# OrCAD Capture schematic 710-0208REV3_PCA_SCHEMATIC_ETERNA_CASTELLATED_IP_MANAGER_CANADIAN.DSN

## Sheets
1 03) CASTLE: size Custom; title: PCA SCH, ETERNA IP CASTELLATED MNGR,CANADIAN; rev: 03; note: 710-0208
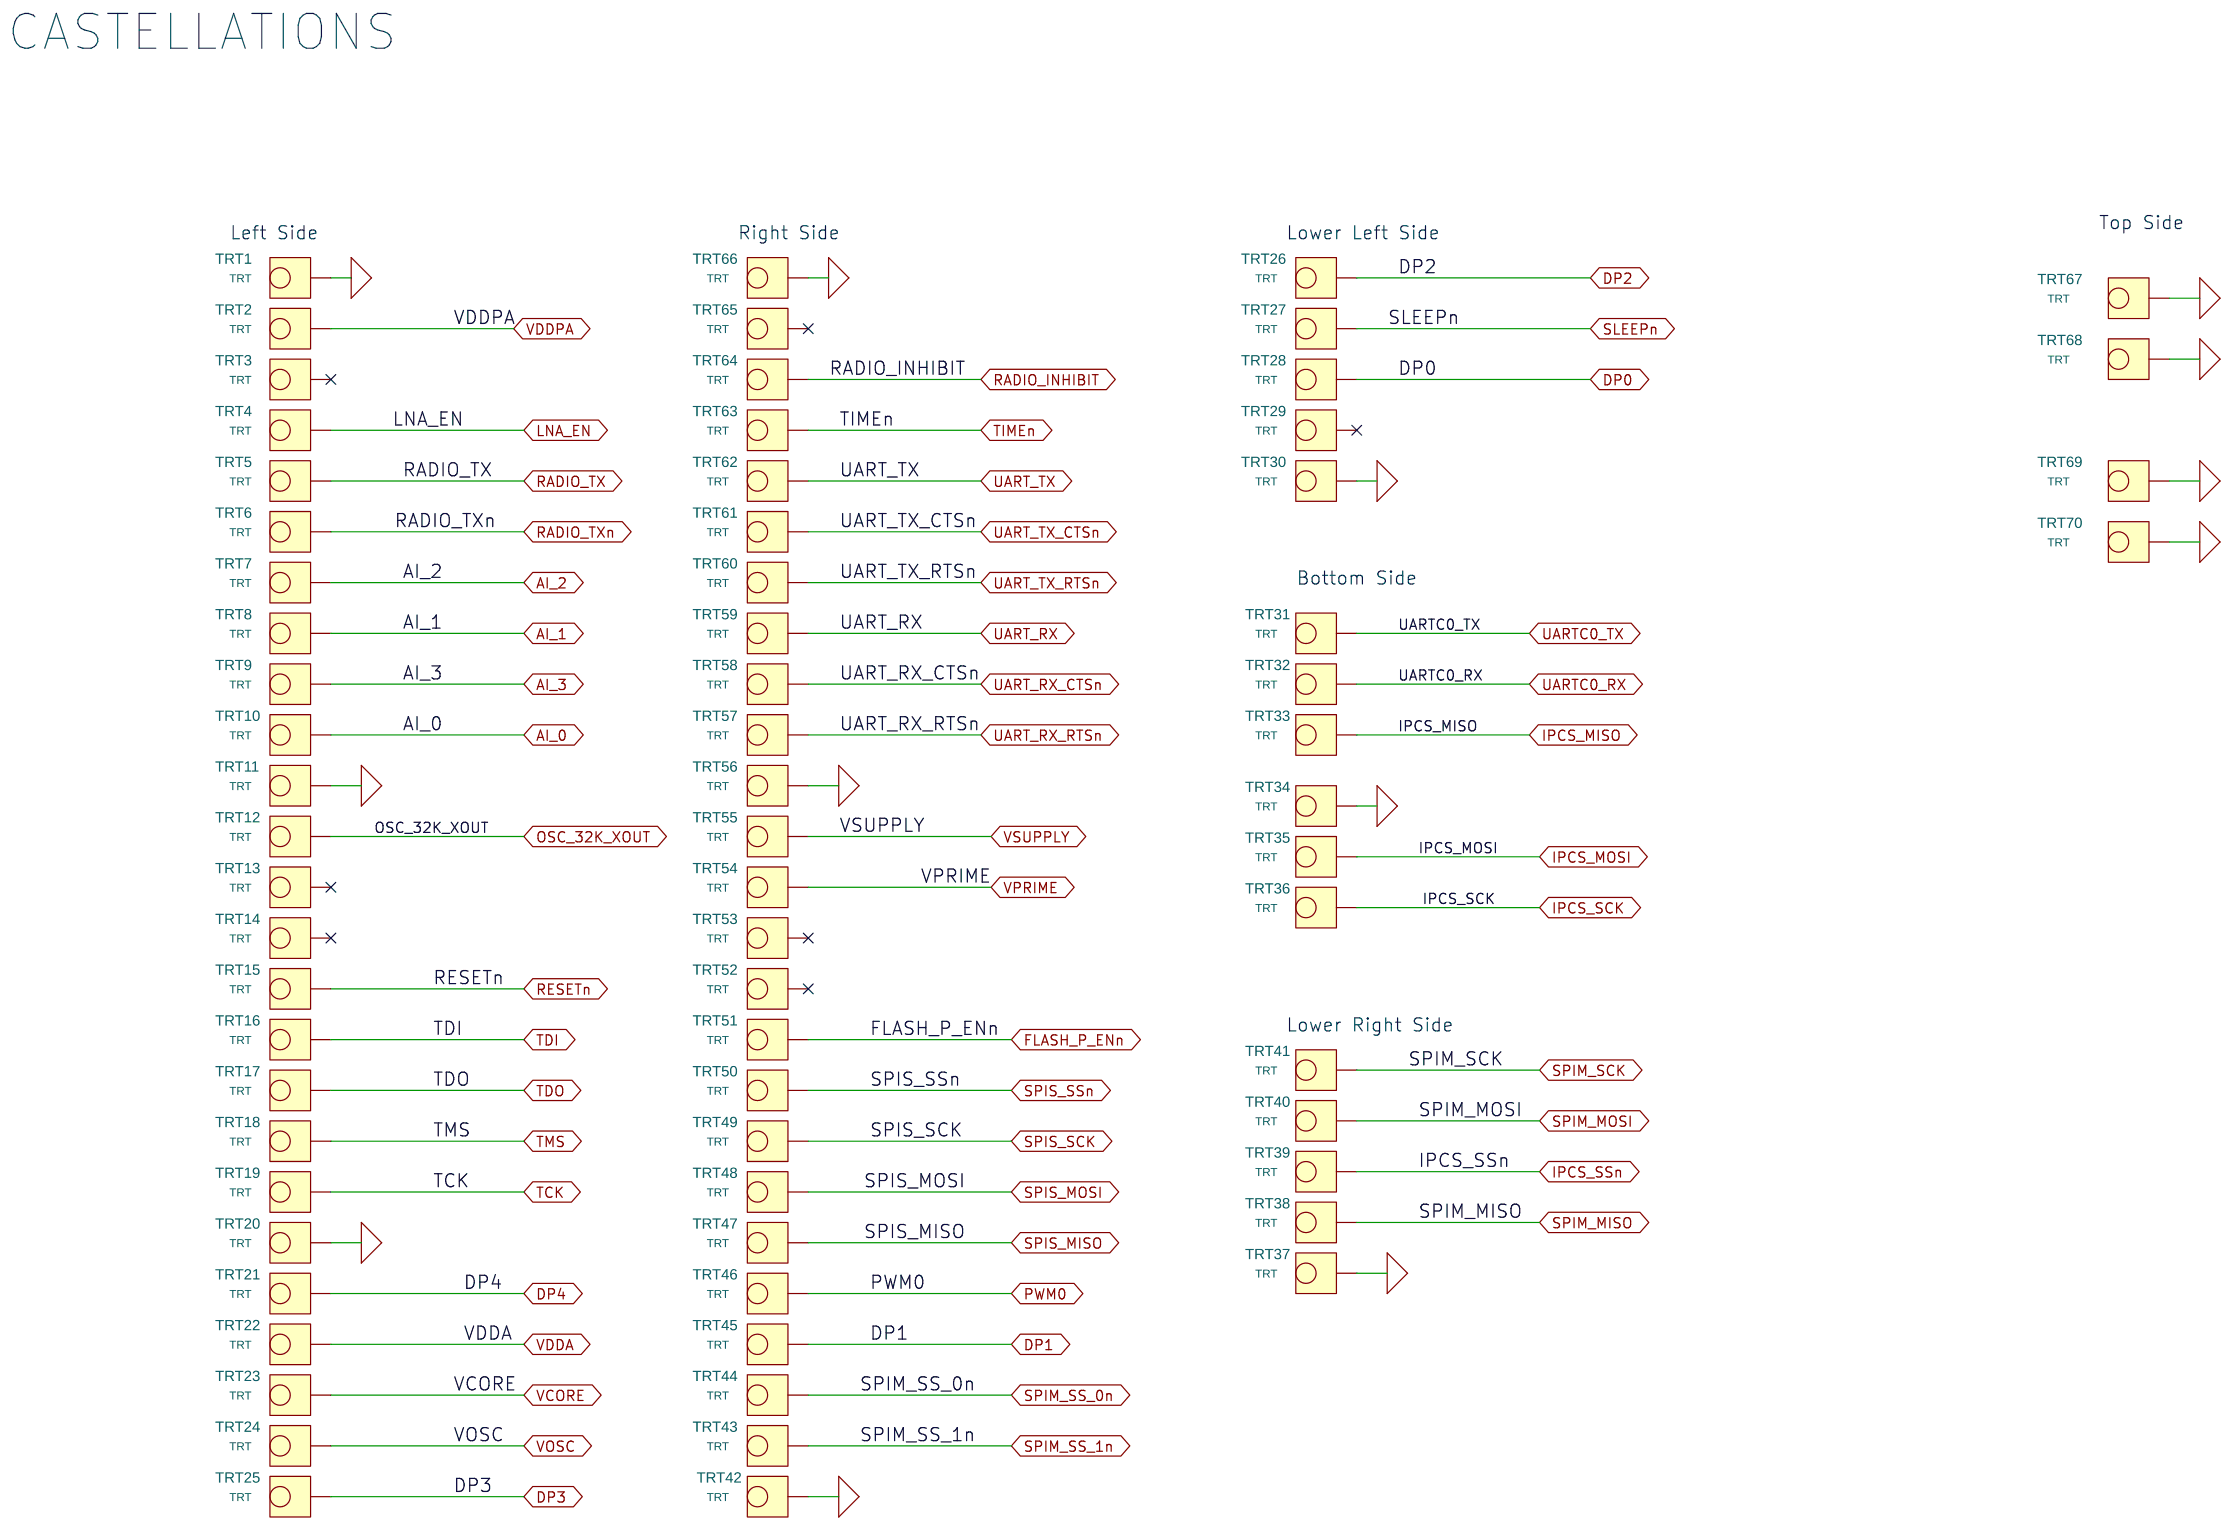
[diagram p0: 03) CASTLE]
2 04) OPTIONS: size Custom
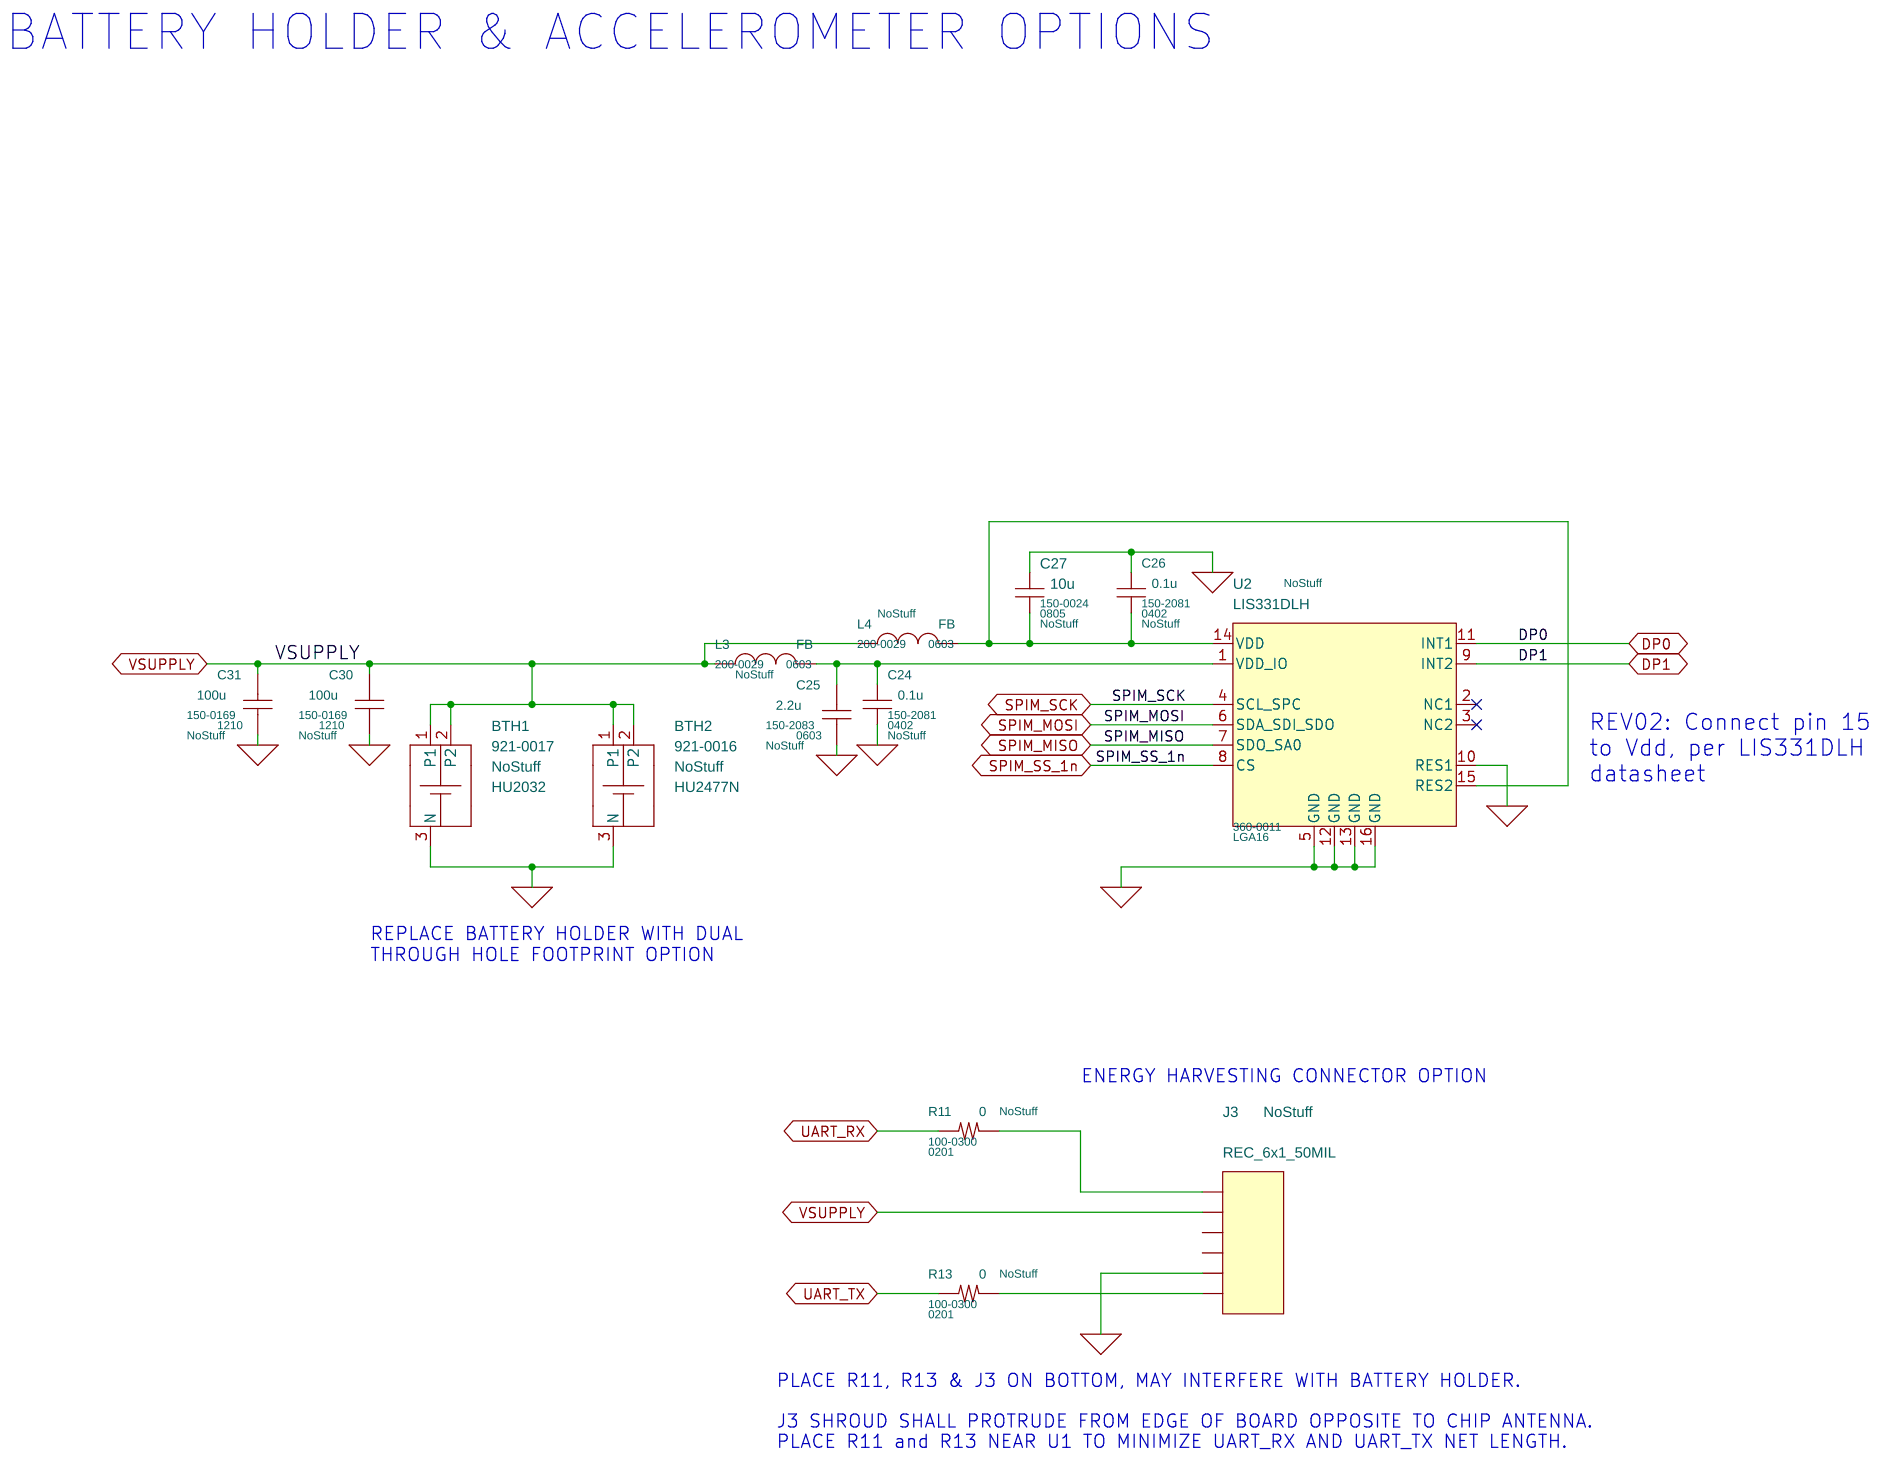
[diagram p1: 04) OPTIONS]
3 01) Title
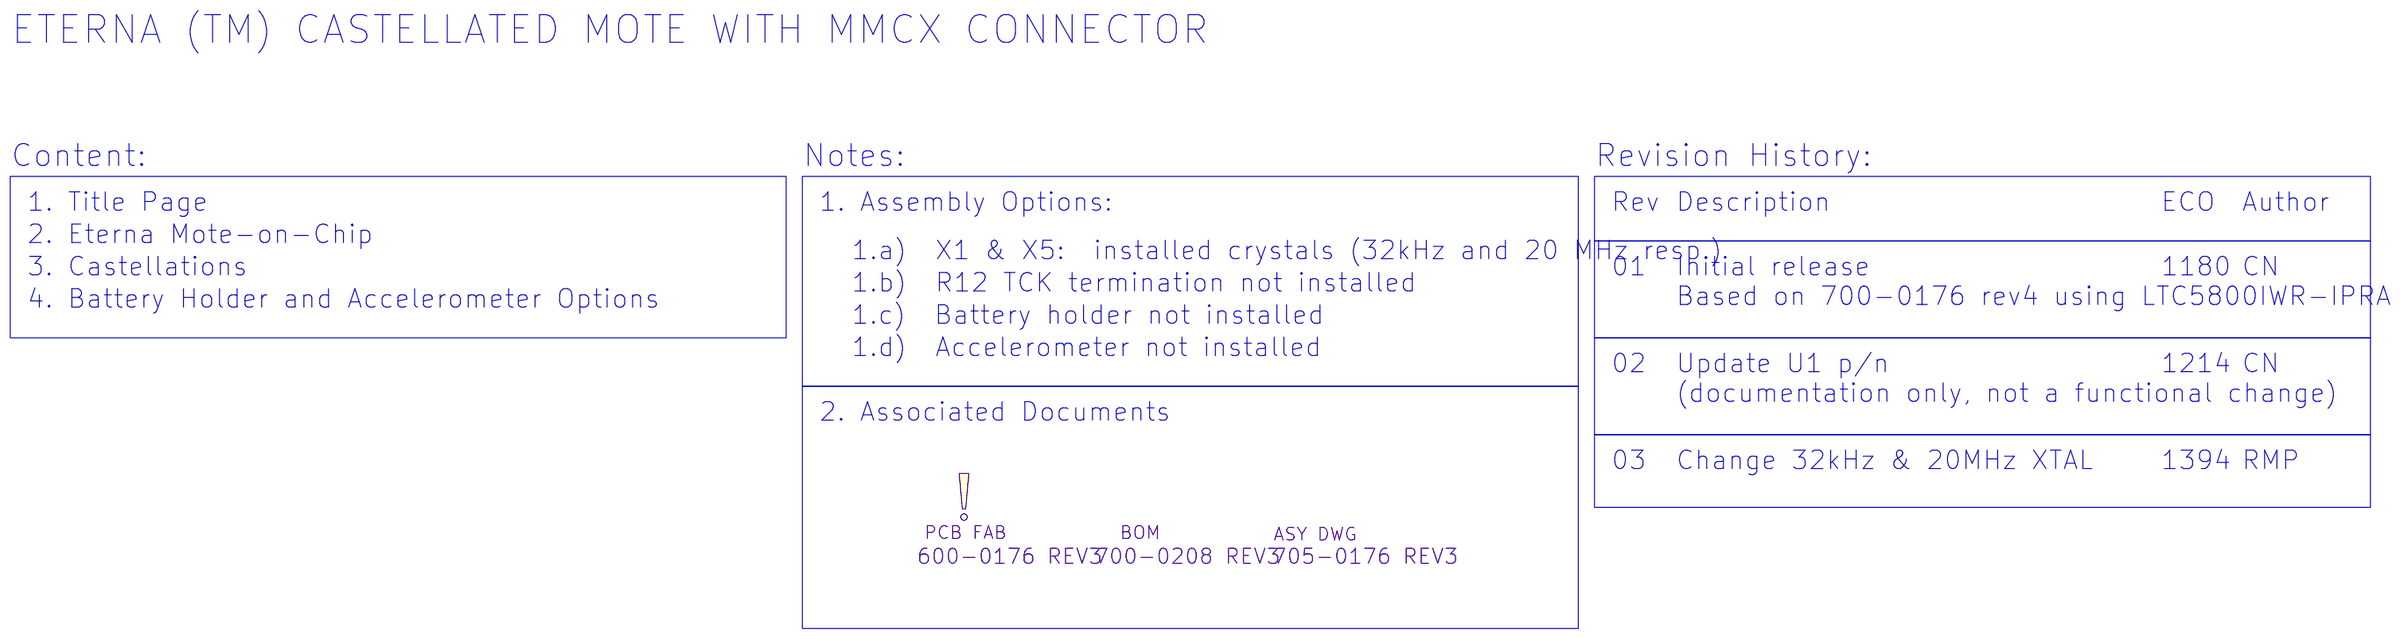
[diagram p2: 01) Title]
4 02) OSKI: size Custom
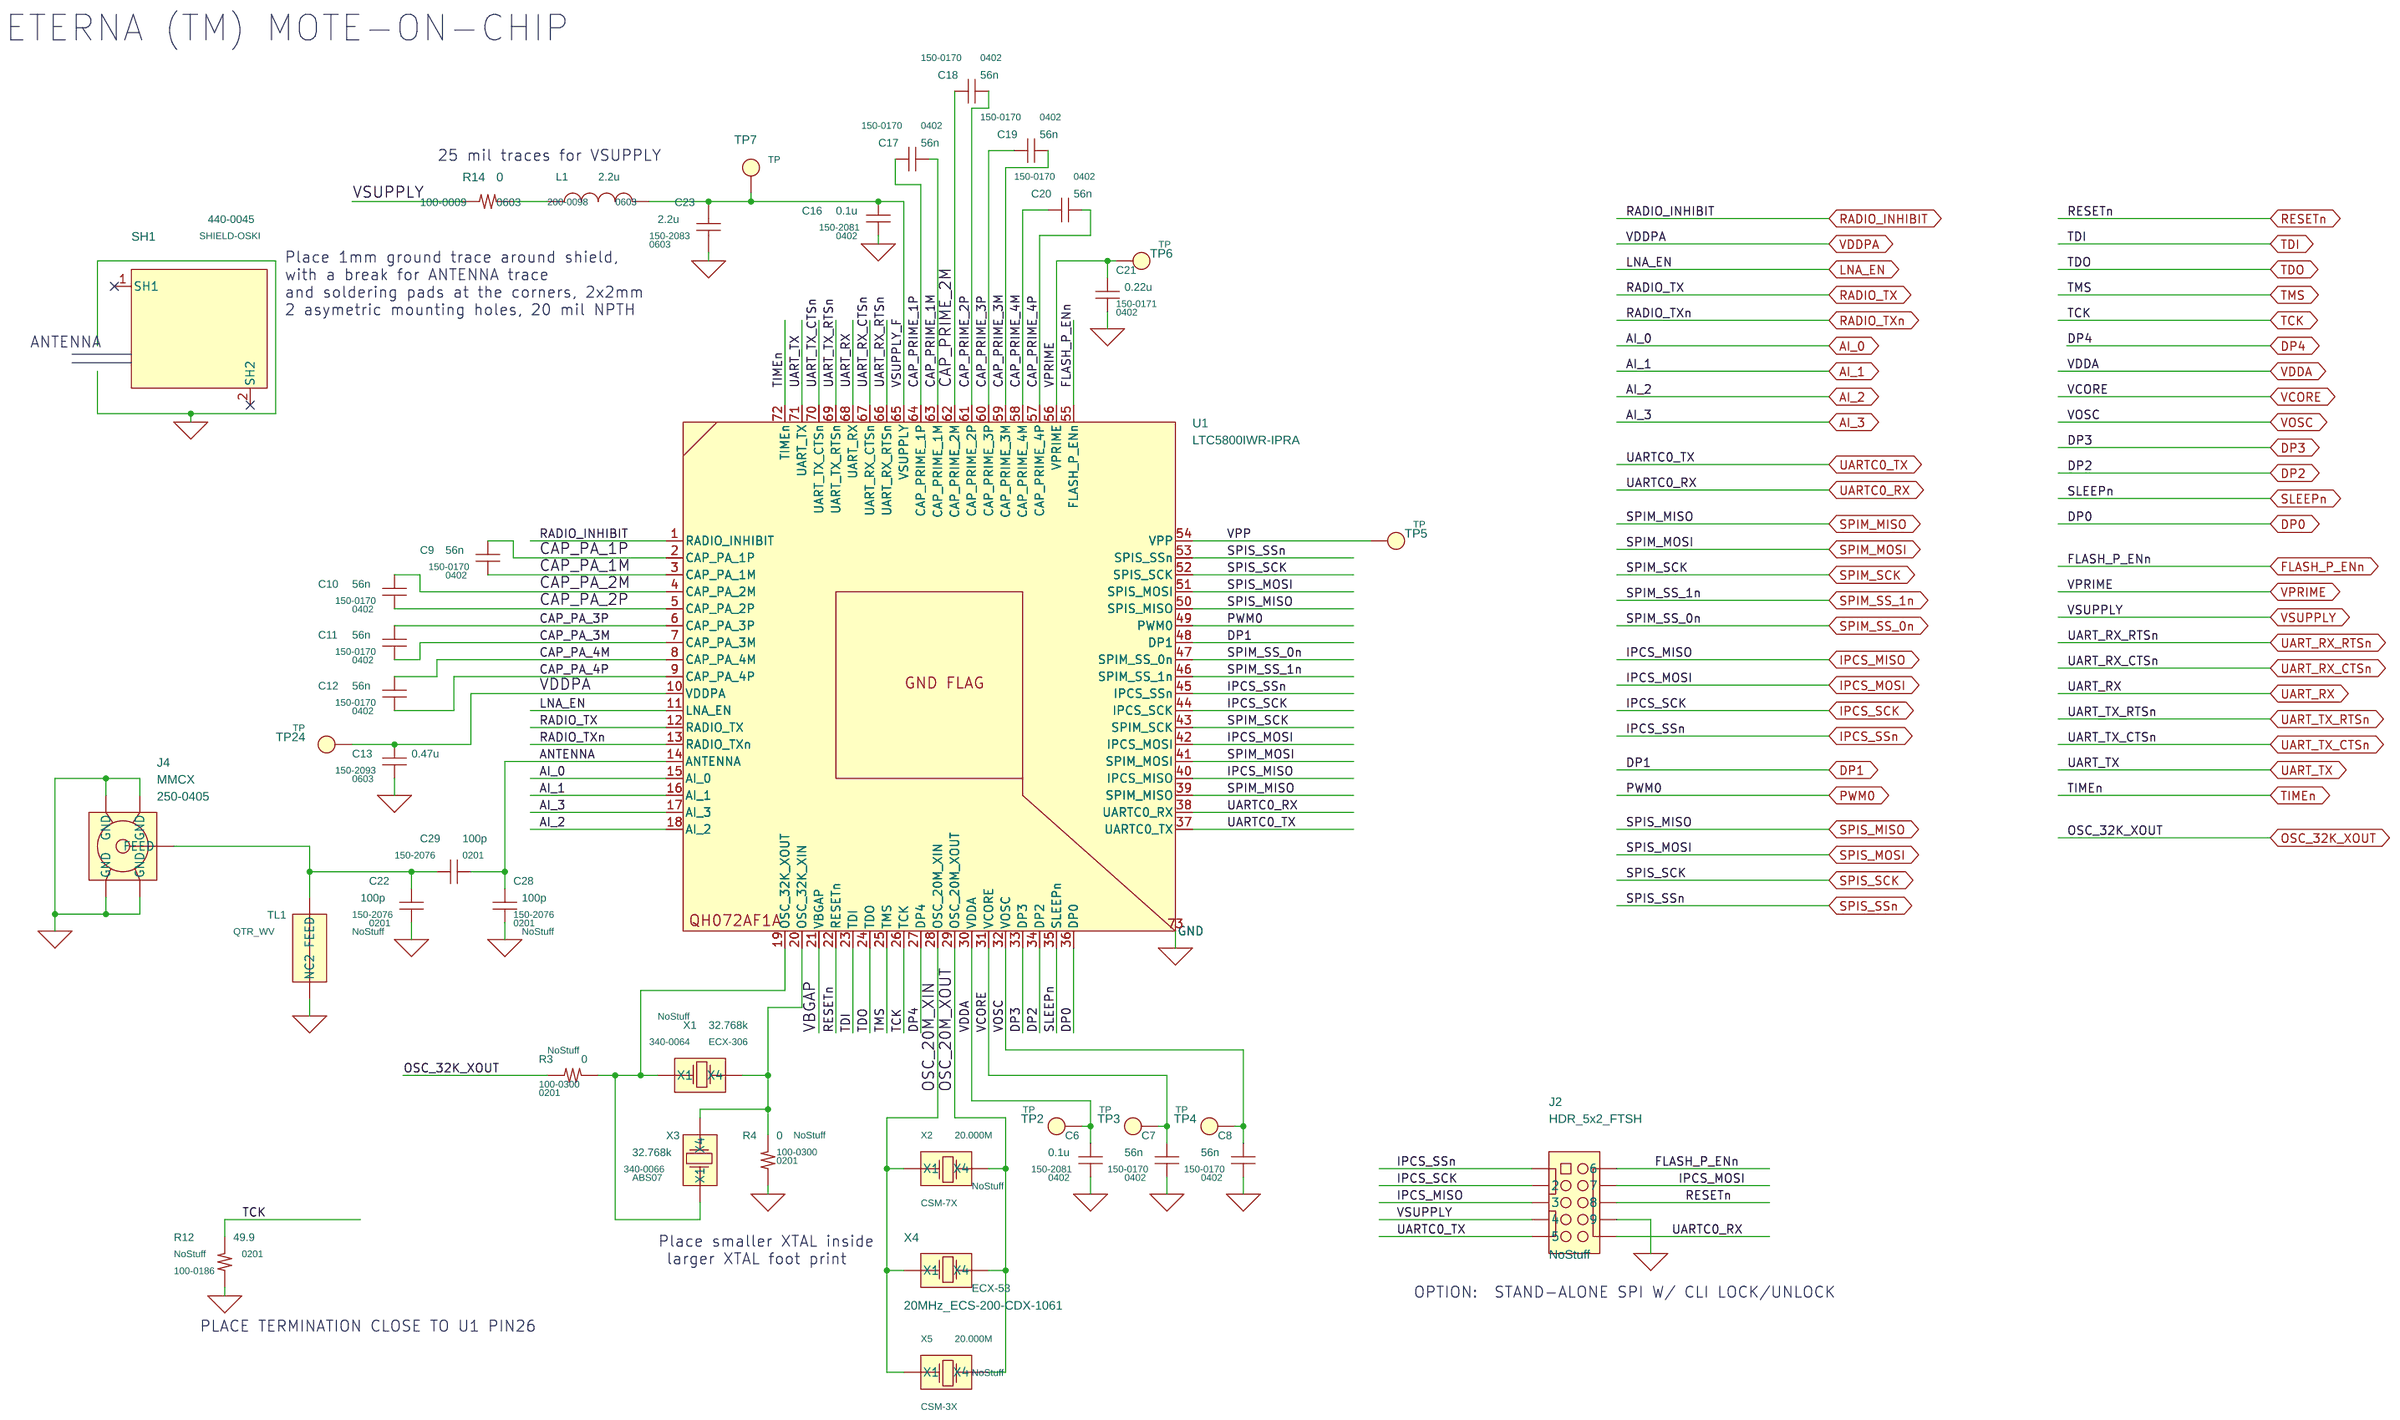
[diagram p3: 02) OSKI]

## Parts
sheet 01) Title
WARNINGL1  CALLOUT_PCB_FAB
WARNINGL3  CALLOUT_BOM
WARNINGL4  CALLOUT_ASSY_DWG
sheet 02) OSKI
C6  0.1u  [0402]
C7  56n  [0402]
C8  56n  [0402]
C9  56n  [0402]
C10  56n  [0402]
C11  56n  [0402]
C12  56n  [0402]
C13  0.47u  [0603]
C16  0.1u  [0402]
C17  56n  [0402]
C18  56n  [0402]
C19  56n  [0402]
C20  56n  [0402]
C21  0.22u  [0402]
C22  100p  [0201]
C23  2.2u  [0603]
C28  100p  [0201]
C29  100p  [0201]
J2  HDR_5x2_FTSH  [FTSH105SM]
J4  COAX_MMCX_PTH  [MMCX]
L1  2.2u  [0603]
R3  0  [0201]
R4  0  [0201]
R12  49.9  [0201]
R14  0  [0603]
SH1  RF Shld Oski  [SHIELD-OSKI]
TL1  FR05  [QTR_WV]
TP2  TP 35Mil  [TP]
TP3  TP 35Mil  [TP]
TP4  TP 35Mil  [TP]
TP5  TP 35Mil  [TP]
TP6  TP 35Mil  [TP]
TP7  TP 35Mil  [TP]
TP24  TP 35Mil  [TP]
U1  LTC5800IWR-IPRA  [QH072AF1A]
X1  32.768k  [ECX-306]
X2  20.000M  [CSM-7X]
X3  32.768k  [ABS07]
X4  20MHz_ECS-200-CDX-1061  [ECX-53]
X5  20.000M  [CSM-3X]
sheet 03) CASTLE
TRT1  TP35_0  [TRT]
TRT2  TP35_0  [TRT]
TRT3  TP35_0  [TRT]
TRT4  TP35_0  [TRT]
TRT5  TP35_0  [TRT]
TRT6  TP35_0  [TRT]
TRT7  TP35_0  [TRT]
TRT8  TP35_0  [TRT]
TRT9  TP35_0  [TRT]
TRT10  TP35_0  [TRT]
TRT11  TP35_0  [TRT]
TRT12  TP35_0  [TRT]
TRT13  TP35_0  [TRT]
TRT14  TP35_0  [TRT]
TRT15  TP35_0  [TRT]
TRT16  TP35_0  [TRT]
TRT17  TP35_0  [TRT]
TRT18  TP35_0  [TRT]
TRT19  TP35_0  [TRT]
TRT20  TP35_0  [TRT]
TRT21  TP35_0  [TRT]
TRT22  TP35_0  [TRT]
TRT23  TP35_0  [TRT]
TRT24  TP35_0  [TRT]
TRT25  TP35_0  [TRT]
TRT26  TP35_0  [TRT]
TRT27  TP35_0  [TRT]
TRT28  TP35_0  [TRT]
TRT29  TP35_0  [TRT]
TRT30  TP35_0  [TRT]
TRT31  TP35_0  [TRT]
TRT32  TP35_0  [TRT]
TRT33  TP35_0  [TRT]
TRT34  TP35_0  [TRT]
TRT35  TP35_0  [TRT]
TRT36  TP35_0  [TRT]
TRT37  TP35_0  [TRT]
TRT38  TP35_0  [TRT]
TRT39  TP35_0  [TRT]
TRT40  TP35_0  [TRT]
TRT41  TP35_0  [TRT]
TRT42  TP35_0  [TRT]
TRT43  TP35_0  [TRT]
TRT44  TP35_0  [TRT]
TRT45  TP35_0  [TRT]
TRT46  TP35_0  [TRT]
TRT47  TP35_0  [TRT]
TRT48  TP35_0  [TRT]
TRT49  TP35_0  [TRT]
TRT50  TP35_0  [TRT]
TRT51  TP35_0  [TRT]
TRT52  TP35_0  [TRT]
TRT53  TP35_0  [TRT]
TRT54  TP35_0  [TRT]
TRT55  TP35_0  [TRT]
TRT56  TP35_0  [TRT]
TRT57  TP35_0  [TRT]
TRT58  TP35_0  [TRT]
TRT59  TP35_0  [TRT]
TRT60  TP35_0  [TRT]
TRT61  TP35_0  [TRT]
TRT62  TP35_0  [TRT]
TRT63  TP35_0  [TRT]
TRT64  TP35_0  [TRT]
TRT65  TP35_0  [TRT]
TRT66  TP35_0  [TRT]
TRT67  TP35_0  [TRT]
TRT68  TP35_0  [TRT]
TRT69  TP35_0  [TRT]
TRT70  TP35_0  [TRT]
sheet 04) OPTIONS
BTH1  HU2032  [HU2032]
BTH2  HU2477N  [HU2477N]
C24  0.1u  [0402]
C25  2.2u  [0603]
C26  0.1u  [0402]
C27  10u  [0805]
C30  100u  [1210]
C31  100u  [1210]
J3  REC_6x1_50MIL  [REC6X1SMRA50]
L3  FB  [0603]
L4  FB  [0603]
R11  0  [0201]
R13  0  [0201]
U2  LIS331DLH  [LGA16]

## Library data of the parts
WARNINGL1 = CALLOUT_PCB_FAB: Part Number: 600-0176 REV3
WARNINGL3 = CALLOUT_BOM: Part Number: 700-0208 REV3
WARNINGL4 = CALLOUT_ASSY_DWG: Part Number: 705-0176 REV3
C6 = C_Generic: Mfg #1: Murata; Mfg #2: GRM033R60J104KE19D; P/N #1: 150-FIX; Part Number: 150-2081; Rating: 16V; Tolerance: 10%
C7 C8 = C_Generic: Mfg #1: Murata; Mfg #2: GRM033R60J104KE19D; P/N #1: 150-FIX; Part Number: 150-0170; Rating: 16V; Tolerance: 10%
C9-C12 C17-C20 = C_Generic: Mfg #1: Murata; Mfg #2: GRM033R60J104KE19D; P/N #1: 150-2081; Part Number: 150-0170; Rating: 16V; Tolerance: 10%
C13 = C_Generic: Mfg #1: Murata; Mfg #2: GRM033R60J104KE19D; P/N #1: 150-2081; Part Number: 150-2093; Rating: 16V; Tolerance: 10%
C16 = C_Generic: Mfg #1: Murata; Mfg #2: GRM033R60J104KE19D; P/N #1: 150-2081; Part Number: 150-2081; Rating: 16V; Tolerance: 10%
C21 = C_Generic: Mfg #1: Murata; Mfg #2: GRM033R60J104KE19D; P/N #1: 150-FIX; Part Number: 150-0171; Rating: 16V; Tolerance: 10%
C22 C28 = C_Generic: Mfg #1: Murata; Mfg #2: GRM033R60J104KE19D; P/N #1: 150-FIX; Part Number: 150-2076; Rating: 16V; Stuff: NoStuff; Tolerance: 10%
C23 = CAP_NP_5: P/N #1: GRM188R71A225KE15D; Part Number: 150-2083; Rating: 10V; Tolerance: 10%
C29 = C_Generic: Mfg #1: Murata; Mfg #2: GRM033R60J104KE19D; P/N #1: 150-FIX; Part Number: 150-2076; Rating: 16V; Tolerance: 10%
J2 = HDR_5x2_50MIL_SM_HALF_SHROUD: Stuff: NoStuff
J4 = COAX_MMCX_PTH_SHORT_PINS: Part Number: 250-0405
L1 = INDUCTOR: P/N #1: LQM18FN2R2K00; Part Number: 200-0098; Tolerance: 10%
R3 R4 R11 R13 = R_Small: Mfg #1: Panasonic; Mfg #2: ERJ-1GEJ104C; P/N #1: 100-0048; Part Number: 100-0300; Rating: 1/16 W; Stuff: NoStuff; Tolerance: 5%
R12 = R_Small: Mfg #1: Panasonic; Mfg #2: ERJ-1GEJ104C; P/N #1: 100-0186; Part Number: 100-0186; Rating: 1/16 W; Stuff: NoStuff; Tolerance: 1%
R14 = R_Small: P/N #1: 100-0058; Part Number: 100-0009; Rating: 1/16 W; Tolerance: 5%
SH1 = CONGO_CAN_2: RF SHIELD SNAKE MOTE; Dist PN: NA; Manuf PN: InDesign xxxx; Part Number: 440-0045
TL1 = Hirose_EFL_8: CONN MMCX JACK STR PCB .115" GOLD; Alternate: Johnson 135-3701-301 (MMCX RA), JST AYU1-1P-02676-120 (U.FL); Dist PN: Digikey J597-ND; Manuf PN: Johnson 135-3701-201
TP2-TP7 TP24 = TP35: Dist PN: NA; Manuf PN: NA
U1 = LTC5800IWR-IPRA
X1 = CITIZEN4_0: Mfg #1: Suntsu; Part Number: 340-0064; Stuff: NoStuff
X2 = XTAL_20.000MHZ_CTRL_ECS-CSM7X: Stuff: NoStuff
X3 = CITIZEN4_0: Mfg #1: Suntsu; Part Number: 340-0066
X4 = XTAL_20.000MHZ_ECS-200-CDX-1061
X5 = XTAL_20.000MHZ_CRTL_ECS-CSM3X: Stuff: NoStuff
TRT1-TRT70 = TP35_2: Dist PN: NA; Manuf PN: NA
BTH1 = BAT_HOLDER_2032_PTH: BATTERY HOLDER, COIN CELL, 2032, TROUGH HOLE; Part Number: 921-0017; Stuff: NoStuff
BTH2 = BAT_HOLDER_2477_PTH: BATTERY HOLDER, COIN CELL, 2477, TROUGH HOLE; Part Number: 921-0016; Stuff: NoStuff
C24 C26 = C_Generic: Mfg #1: Murata; Mfg #2: GRM033R60J104KE19D; P/N #1: 150-FIX; Part Number: 150-2081; Rating: 16V; Stuff: NoStuff; Tolerance: 10%
C25 = CAP_NP_5: P/N #1: GRM188R71A225KE15D; Part Number: 150-2083; Rating: 10V; Stuff: NoStuff; Tolerance: 10%
C27 = C_Generic: Composition: X5R; Dielectric: X5R; Dist PN: Digikey PCC2225CT-ND; Part Number: 150-0024; Stuff: NoStuff; Tolerance: 20%
C30 C31 = CAP_NP_5: P/N #1: GRM188R71A225KE15D; Part Number: 150-0169; Rating: 10V; Stuff: NoStuff; Tolerance: 10%
J3 = REC_6x1_50MIL_SM_RA_SHROUD: Stuff: NoStuff
L3 L4 = INDUCTOR_0: IND FB 0603; Part Number: 200-0029; Stuff: NoStuff
U2 = TPS3307_1: Part Number: 360-0011; Stuff: NoStuff

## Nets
GND_SIGNAL: BTH1.3(N) BTH2.3(N) C6.2 C7.2 C8.2 C13.2 C16.2 C21.2 C22.2 C23.2 C24.2 C25.2 C26.1 C27.2 C28.2 C30.2 C31.2 J2.8(9) J3.5 J4.2(GND) J4.3(GND) J4.4(GND) J4.5(GND) R4.1 R12.1 TL1.2(NC2) TRT1.1(TP) TRT11.1(TP) TRT20.1(TP) TRT30.1(TP) TRT34.1(TP) TRT37.1(TP) TRT42.1(TP) TRT56.1(TP) TRT66.1(TP) TRT67.1(TP) TRT68.1(TP) TRT69.1(TP) TRT70.1(TP) U1.73(GND) U2.5(GND) U2.10(RES1) U2.12(GND) U2.13(GND) U2.16(GND)
VDDA: C6.1 TP2.1(TP) TRT22.1(TP) U1.30(VDDA)
VDDPA: C13.1 TP24.1(TP) TRT2.1(TP) U1.10(VDDPA)
AI_0: TRT10.1(TP) U1.15(AI_0)
AI_1: TRT8.1(TP) U1.16(AI_1)
AI_2: TRT7.1(TP) U1.18(AI_2)
AI_3: TRT9.1(TP) U1.17(AI_3)
ANTENNA: C28.1 C29.2 U1.14(ANTENNA)
CAP_PA_1M: C9.2 U1.3(CAP_PA_1M)
CAP_PA_1P: C9.1 U1.2(CAP_PA_1P)
CAP_PA_2M: C10.1 U1.4(CAP_PA_2M)
CAP_PA_2P: C10.2 U1.5(CAP_PA_2P)
CAP_PA_3M: C11.2 U1.7(CAP_PA_3M)
CAP_PA_3P: C11.1 U1.6(CAP_PA_3P)
CAP_PA_4M: C12.1 U1.8(CAP_PA_4M)
CAP_PA_4P: C12.2 U1.9(CAP_PA_4P)
CAP_PRIME_1M: C17.2 U1.63(CAP_PRIME_1M)
CAP_PRIME_1P: C17.1 U1.64(CAP_PRIME_1P)
CAP_PRIME_2M: C18.1 U1.62(CAP_PRIME_2M)
CAP_PRIME_2P: C18.2 U1.61(CAP_PRIME_2P)
CAP_PRIME_3M: C19.2 U1.59(CAP_PRIME_3M)
CAP_PRIME_3P: C19.1 U1.60(CAP_PRIME_3P)
CAP_PRIME_4M: C20.1 U1.58(CAP_PRIME_4M)
CAP_PRIME_4P: C20.2 U1.57(CAP_PRIME_4P)
DP0: TRT28.1(TP) U1.36(DP0) U2.11(INT1)
DP1: TRT45.1(TP) U1.48(DP1) U2.9(INT2)
DP2: TRT26.1(TP) U1.34(DP2)
DP3: TRT25.1(TP) U1.33(DP3)
DP4: TRT21.1(TP) U1.27(DP4)
FLASH_P_ENn: J2.2(6) TRT51.1(TP) U1.55(FLASH_P_ENn)
IPCS_MISO: J2.5(3) TRT33.1(TP) U1.40(IPCS_MISO)
IPCS_MOSI: J2.4(7) TRT35.1(TP) U1.42(IPCS_MOSI)
IPCS_SCK: J2.3(2) TRT36.1(TP) U1.44(IPCS_SCK)
IPCS_SSn: J2.1 TRT39.1(TP) U1.45(IPCS_SSn)
LNA_EN: TRT4.1(TP) U1.11(LNA_EN)
OSC_20M_XIN: U1.28(OSC_20M_XIN) X2.1(X1) X4.1(X1) X5.1(X1)
OSC_20M_XOUT: U1.29(OSC_20M_XOUT) X2.2(X4) X4.2(X4) X5.2(X4)
OSC_32K_XOUT: R3.1 TRT12.1(TP)
PWM0: TRT46.1(TP) U1.49(PWM0)
RADIO_INHIBIT: TRT64.1(TP) U1.1(RADIO_INHIBIT)
RADIO_TX: TRT5.1(TP) U1.12(RADIO_TX)
RADIO_TXn: TRT6.1(TP) U1.13(RADIO_TXn)
RESETn: J2.6(8) TRT15.1(TP) U1.22(RESETn)
SLEEPn: TRT27.1(TP) U1.35(SLEEPn)
SPIM_MISO: TRT38.1(TP) U1.39(SPIM_MISO) U2.7(SDO_SA0)
SPIM_MOSI: TRT40.1(TP) U1.41(SPIM_MOSI) U2.6(SDA_SDI_SDO)
SPIM_SCK: TRT41.1(TP) U1.43(SPIM_SCK) U2.4(SCL_SPC)
SPIM_SS_0n: TRT44.1(TP) U1.47(SPIM_SS_0n)
SPIM_SS_1n: TRT43.1(TP) U1.46(SPIM_SS_1n) U2.8(CS)
SPIS_MISO: TRT47.1(TP) U1.50(SPIS_MISO)
SPIS_MOSI: TRT48.1(TP) U1.51(SPIS_MOSI)
SPIS_SCK: TRT49.1(TP) U1.52(SPIS_SCK)
SPIS_SSn: TRT50.1(TP) U1.53(SPIS_SSn)
TCK: R12.2 TRT19.1(TP) U1.26(TCK)
TDI: TRT16.1(TP) U1.23(TDI)
TDO: TRT17.1(TP) U1.24(TDO)
TIMEn: TRT63.1(TP) U1.72(TIMEn)
TMS: TRT18.1(TP) U1.25(TMS)
UART_RX: R11.1 TRT59.1(TP) U1.68(UART_RX)
UART_RX_CTSn: TRT58.1(TP) U1.67(UART_RX_CTSn)
UART_RX_RTSn: TRT57.1(TP) U1.66(UART_RX_RTSn)
UART_TX: R13.1 TRT62.1(TP) U1.71(UART_TX)
UART_TX_CTSn: TRT61.1(TP) U1.70(UART_TX_CTSn)
UART_TX_RTSn: TRT60.1(TP) U1.69(UART_TX_RTSn)
UARTC0_RX: J2.10 TRT32.1(TP) U1.38(UARTC0_RX)
UARTC0_TX: J2.9(5) TRT31.1(TP) U1.37(UARTC0_TX)
VBGAP: U1.21(VBGAP)
VCORE: C7.1 TP3.1(TP) TRT23.1(TP) U1.31(VCORE)
VOSC: C8.1 TP4.1(TP) TRT24.1(TP) U1.32(VOSC)
VPP: TP5.1(TP) U1.54(VPP)
VPRIME: C21.1 TP6.1(TP) TRT54.1(TP) U1.56(VPRIME)
VSUPPLY: BTH1.1(P1) BTH1.2(P2) BTH2.1(P1) BTH2.2(P2) C30.1 C31.1 J2.7(4) J3.2 L3.2 L4.2 R14.1 TRT55.1(TP)
VSUPPLY_F: C16.1 C23.1 L1.2 TP7.1(TP) U1.65(VSUPPLY)
N17767888: R4.2 U1.20(OSC_32K_XIN) X1.2(X4) X3.2(X4)
N17768343: R3.2 U1.19(OSC_32K_XOUT) X1.1(X1) X3.1(X1)
N19818559: C24.1 C25.1 L3.1 U2.1(VDD_IO)
N19821129: C26.2 C27.1 L4.1 U2.14(VDD) U2.15(RES2)
N19983424: C22.1 C29.1 J4.1(FEED) TL1.1(FEED)
N19987882: L1.1 R14.2
N20383545: J3.6 R13.2
N20383549: J3.1 R11.2

Not connected (* = marked no-connect by the designer): J3 3 4; SH1 1(SH1)* 2(SH2)*; TRT3 1(TP)*; TRT13 1(TP)*; TRT14 1(TP)*; TRT29 1(TP)*; TRT52 1(TP)*; TRT53 1(TP)*; TRT65 1(TP)*; U2 2(NC1)* 3(NC2)*

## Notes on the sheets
sheet 1
- CASTELLATIONS
- Left Side
- Right Side
- Lower Left Side
- Top Side
- Bottom Side
- Lower Right Side
sheet 2
- BATTERY HOLDER & ACCELEROMETER OPTIONS
- REV02: Connect pin 15
  to Vdd, per LIS331DLH
  datasheet
- REPLACE BATTERY HOLDER WITH DUAL
  THROUGH HOLE FOOTPRINT OPTION
- ENERGY HARVESTING CONNECTOR OPTION
- PLACE R11, R13 & J3 ON BOTTOM, MAY INTERFERE WITH BATTERY HOLDER.
- J3 SHROUD SHALL PROTRUDE FROM EDGE OF BOARD OPPOSITE TO CHIP ANTENNA.
- PLACE R11 and R13 NEAR U1 TO MINIMIZE UART_RX AND UART_TX NET LENGTH.
sheet 3
- ETERNA (TM) CASTELLATED MOTE WITH MMCX CONNECTOR
- Content:
- Notes:
- Revision History:
- 1. Title Page
- 1. Assembly Options:
- Rev
- Description
- ECO
- Author
- 2. Eterna Mote-on-Chip
- 1.a)  X1 & X5:  installed crystals (32kHz and 20 MHz resp.)
- 3. Castellations
- 01
- Initial release
  Based on 700-0176 rev4 using LTC5800IWR-IPRA
- 1180
- CN
- 4. Battery Holder and Accelerometer Options
- 1.b)  R12 TCK termination not installed
- 1.c)  Battery holder not installed
- 1.d)  Accelerometer not installed
- 02
- Update U1 p/n
  (documentation only, not a functional change)
- 1214
- CN
- 2. Associated Documents
- 03
- Change 32kHz & 20MHz XTAL
- 1394
- RMP
sheet 4
- ETERNA (TM) MOTE-ON-CHIP
- 25 mil traces for VSUPPLY
- Place 1mm ground trace around shield,
  with a break for ANTENNA trace
  and soldering pads at the corners, 2x2mm
  2 asymetric mounting holes, 20 mil NPTH
- ANTENNA
- Place smaller XTAL inside
   larger XTAL foot print
- OPTION:  STAND-ALONE SPI W/ CLI LOCK/UNLOCK
- PLACE TERMINATION CLOSE TO U1 PIN26
